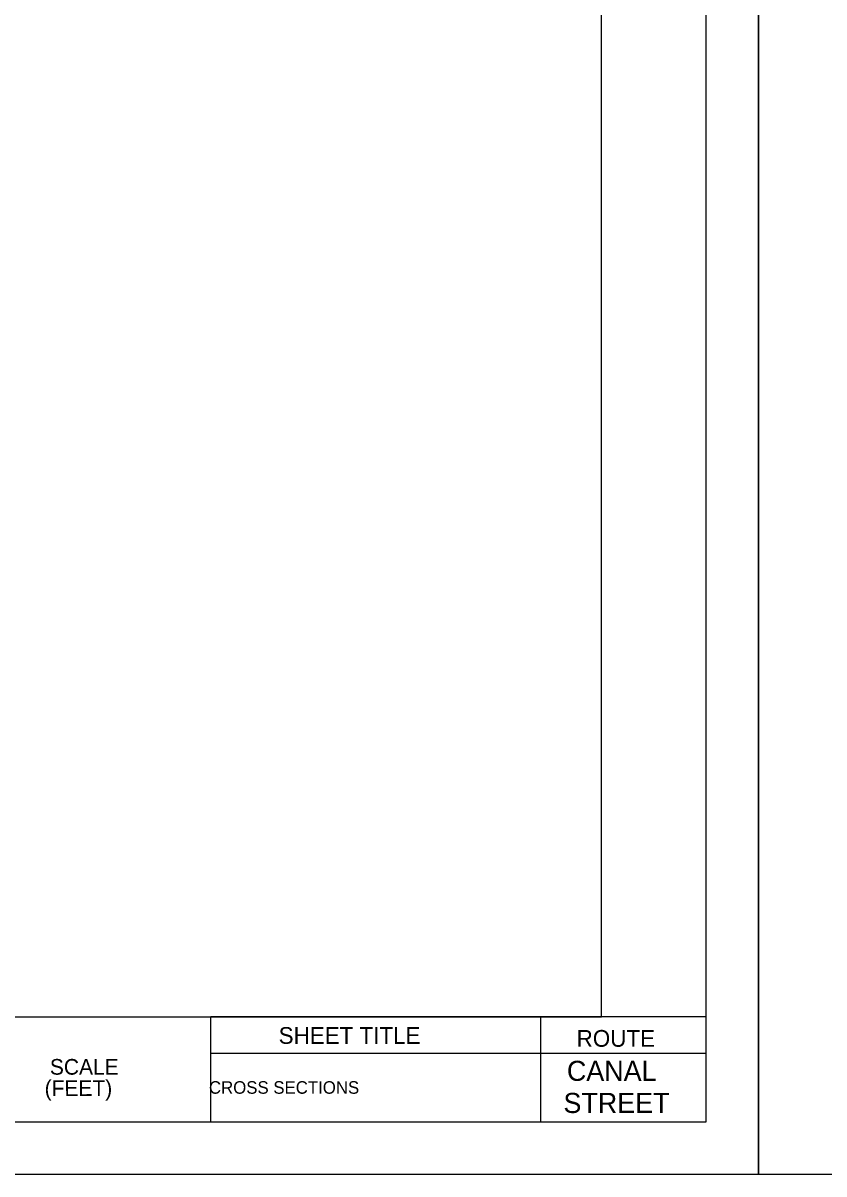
# Model space of a CAD drawing. Extents: x 1797478 to 1808916, y 246529 to 250952.
# Drawn here: x 1802385.7 to 1802462.3, y 250064.4 to 250174.4 of the extents above; entities that cross this region are included whole.
import ezdxf

# ---------------------------------------------------------------- set-up
doc = ezdxf.new("R2010")
doc.units = 0
for name, color, linetype in [('ANNO-SHT', 7, 'Continuous'), ('ANNO-SYMB', 7, 'Continuous'), ('ANNO-TXT', 7, 'Continuous'), ('Level 6', 7, 'Continuous'), ('Level 62', 7, 'Continuous'), ('SHT-BDR', 7, 'Continuous'), ('SHT-BNDRY', 7, 'Continuous')]:
    doc.layers.add(name, color=color, linetype=linetype)

msp = doc.modelspace()

# ---------------------------------------------------------------- linework, layer by layer
at = {"layer": 'ANNO-TXT'}
for p, q in [((1802403.66, 250075.96), (1802435.19, 250075.96)), ((1802435.19, 250075.96), (1802451, 250075.96))]:
    msp.add_line(p, q, dxfattribs=at)
at = {"layer": 'Level 6'}
msp.add_line((1802451, 250079.43), (1802403.66, 250079.43), dxfattribs=at)
at = {"layer": 'Level 62'}
for points in [[(1802116, 250064.42), (1802456, 250064.42), (1802456, 250284.42), (1802116, 250284.42)], [(1802456, 250064.42), (1802796, 250064.42), (1802796, 250284.42), (1802456, 250284.42)]]:
    msp.add_lwpolyline(points, close=True, dxfattribs=at)
at = {"layer": 'SHT-BDR'}
msp.add_lwpolyline([(1802141, 250079.43), (1802441, 250079.43), (1802441, 250269.43), (1802141, 250269.43)], close=True, dxfattribs=at)
at = {"layer": 'SHT-BNDRY'}
for p, q in [((1802403.66, 250069.42), (1802403.66, 250079.43)), ((1802435.19, 250069.42), (1802435.19, 250079.43))]:
    msp.add_line(p, q, dxfattribs=at)
msp.add_lwpolyline([(1802128.5, 250069.42), (1802451, 250069.42), (1802451, 250279.42), (1802128.5, 250279.42)], close=True, dxfattribs=at)

# ---------------------------------------------------------------- texts
at = {"layer": 'ANNO-SHT'}
for s, height, p in [(' CANAL ', 1.92, (1802436.98, 250073.32)), ('          CROSS SECTIONS          ', 1.2, (1802399.03, 250072.09)), (' STREET ', 1.92, (1802436.65, 250070.25))]:
    msp.add_text(s, height=height, rotation=360, dxfattribs=at).set_placement(p)
at = {"layer": 'ANNO-SYMB'}
for s, p in [('SCALE', (1802388.29, 250073.91)), ('(FEET)', (1802387.79, 250071.88))]:
    msp.add_text(s, height=1.499, rotation=0.0572, dxfattribs=at).set_placement(p)
at = {"layer": 'ANNO-TXT'}
for s, p in [('SHEET TITLE', (1802410.15, 250076.86)), ('ROUTE', (1802438.62, 250076.58))]:
    msp.add_text(s, height=1.6, dxfattribs=at).set_placement(p)

doc.saveas('drawing.dxf')
